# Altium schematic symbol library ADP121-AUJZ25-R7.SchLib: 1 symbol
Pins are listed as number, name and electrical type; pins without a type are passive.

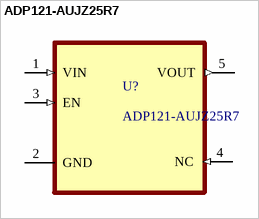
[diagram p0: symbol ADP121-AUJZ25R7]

## ADP121-AUJZ25R7
designator U?
Linear Voltage Regulator IC 1 Output 150mA TSOT-5; MF: Analog Devices
footprint ADP121-AUJZ25-R7
pins: 1 VIN (in), 2 GND, 3 EN (in), 4 NC (in), 5 VOUT (out)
